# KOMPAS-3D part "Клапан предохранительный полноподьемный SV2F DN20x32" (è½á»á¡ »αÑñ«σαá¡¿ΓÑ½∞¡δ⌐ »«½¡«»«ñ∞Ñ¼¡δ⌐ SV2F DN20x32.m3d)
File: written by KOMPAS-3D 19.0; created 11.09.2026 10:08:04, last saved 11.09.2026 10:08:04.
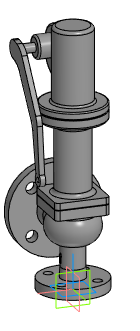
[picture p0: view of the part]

Document properties: Автор: elist; Организация: HP; Полное имя файла: Z:\3.Личные\sachek\Dendor\_3D для проектировщиков\5.9 SV2F. Клапан предохранительный полноподьемный\SV2F_STP\Клапан предохранительный полноподьемный SV2F DN20x32.m3d

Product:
- Part/product: Клапан предохранительный полноподьемный SV2F DN20x32

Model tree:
1. Операция без истории:1  (labels: Клапан предохранительный полноподьемный SV2F DN20x32)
